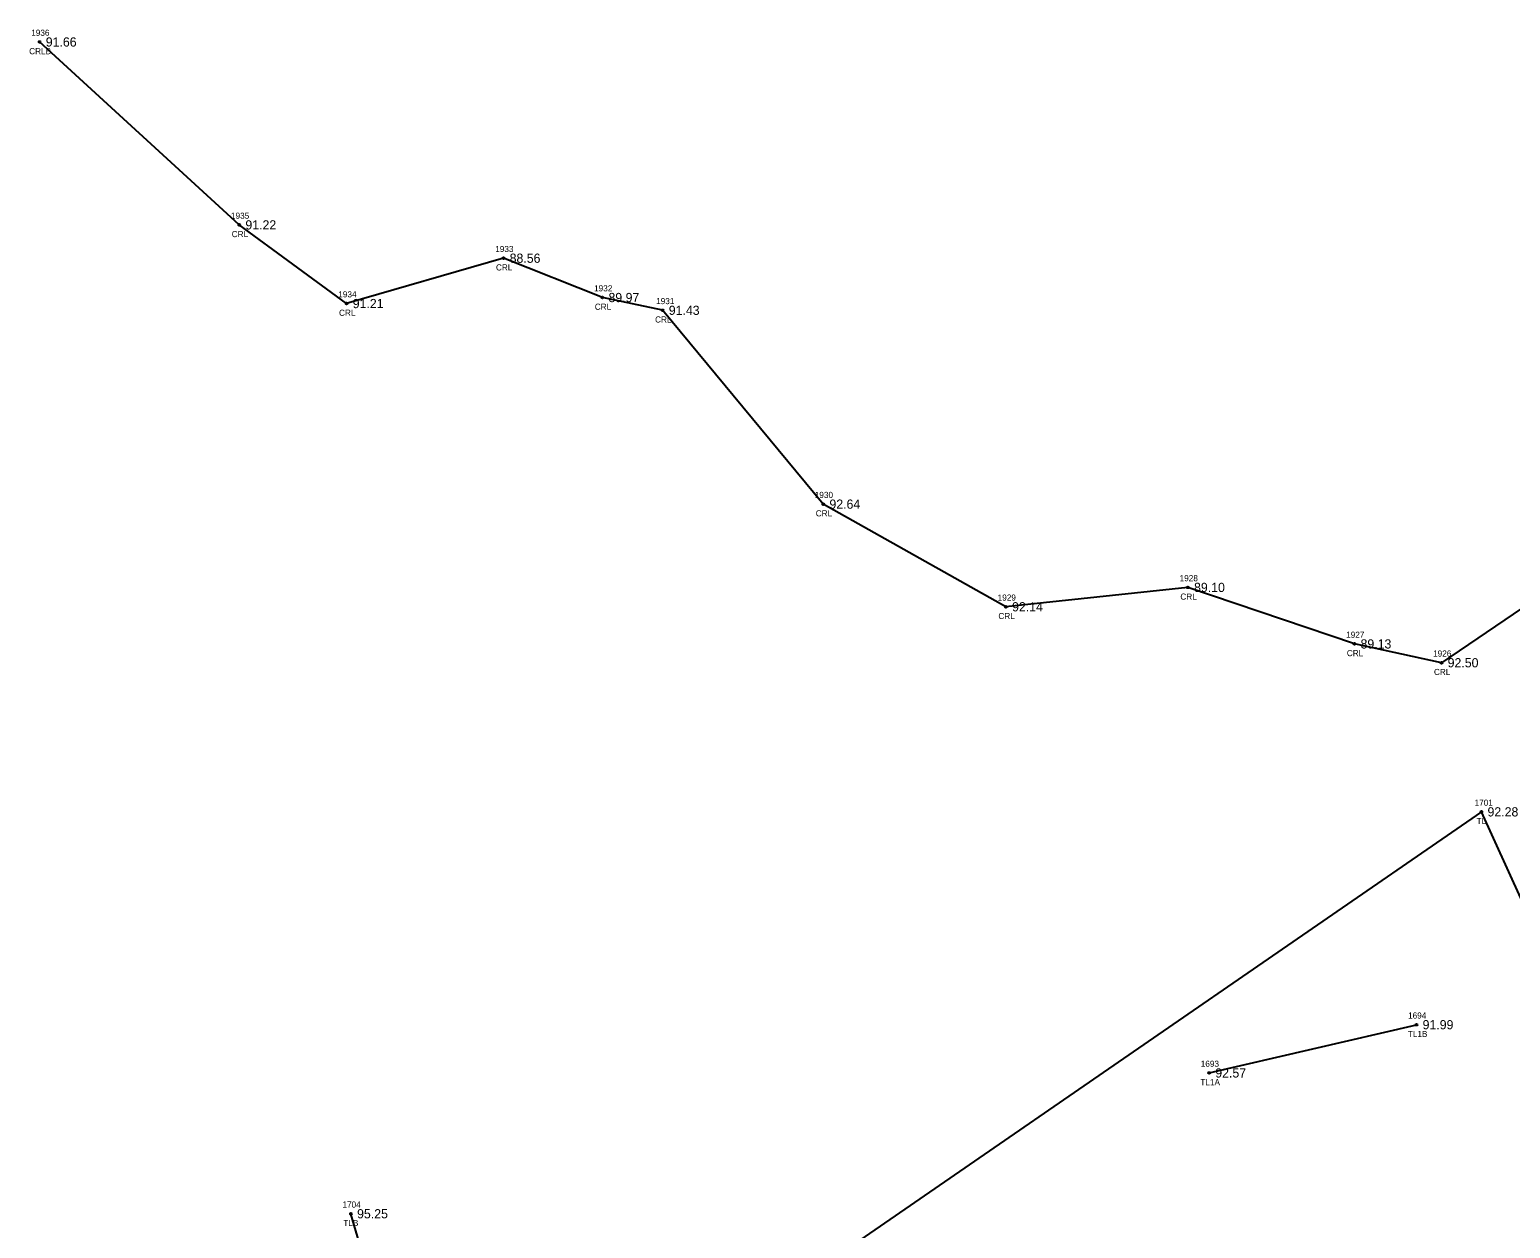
# Model space of a CAD drawing. Extents: x 2529517 to 2532038, y 935000 to 936944.
# Drawn here: x 2530793.2 to 2531034.4, y 935968.4 to 936163.8 of the extents above; entities that cross this region are included whole.
import ezdxf

# ---------------------------------------------------------------- set-up
doc = ezdxf.new("R2010")
doc.units = 0
for name, color, linetype in [('RD_EX_H2O', 7, 'Continuous'), ('RD_EX_H2O_txCode', 7, 'Continuous'), ('RD_EX_TX_H2O_ELEV', 7, 'Continuous'), ('RD_EX_TX_VEG_ELEV', 7, 'Continuous'), ('RD_EX_VEG', 7, 'Continuous'), ('RD_EX_VEG_txCode', 7, 'Continuous'), ('RD_SMD_Locator', 7, 'Continuous')]:
    doc.layers.add(name, color=color, linetype=linetype)

msp = doc.modelspace()

# ---------------------------------------------------------------- linework, layer by layer
at = {"layer": 'RD_EX_H2O'}
msp.add_lwpolyline([(2531078.88, 935952.28), (2531078.88, 935952.28), (2531082.9, 935955.37), (2531071.89, 935962.43), (2531052.52, 935981.82), (2531042.66, 936018.54), (2531050.4, 936038.59), (2531079.35, 936050.48), (2531076.46, 936052.29), (2531062.77, 936059.41), (2531060.27, 936060.12), (2531061.98, 936077.76), (2531053.99, 936081.48), (2531023.23, 936060.57), (2531009.04, 936063.64), (2530981.92, 936072.85), (2530952.28, 936069.69), (2530922.53, 936086.42), (2530896.36, 936118.01), (2530886.54, 936120.09), (2530870.44, 936126.5), (2530844.88, 936119.11), (2530827.4, 936131.93), (2530794.88, 936161.74)], dxfattribs=at)
at = {"layer": 'RD_EX_VEG'}
msp.add_line((2530985.38, 935993.72), (2531019.15, 936001.58), dxfattribs=at)
msp.add_lwpolyline([(2531065.97, 935956.74), (2531029.72, 936036.27), (2530913.11, 935955.89), (2530857.85, 935929), (2530845.59, 935970.77)], dxfattribs=at)
at = {"layer": 'RD_SMD_Locator'}
for centre in [(2530794.88, 936161.74), (2530827.4, 936131.93), (2530870.44, 936126.5), (2530844.88, 936119.11), (2530886.54, 936120.09), (2530896.36, 936118.01), (2530922.53, 936086.42), (2530981.92, 936072.85), (2530952.28, 936069.69), (2531009.04, 936063.64), (2531023.23, 936060.57), (2531029.72, 936036.27), (2531019.15, 936001.58), (2530985.38, 935993.72), (2530845.59, 935970.77)]:
    msp.add_circle(centre, 0.15, dxfattribs=at)

# ---------------------------------------------------------------- texts
at = {"layer": 'RD_EX_H2O_txCode'}
for s, p in [('1936', (2530793.51, 936162.74)), ('CRLB', (2530793.18, 936159.74)), ('1935', (2530826.05, 936132.93)), ('CRL', (2530826.17, 936129.93)), ('1933', (2530869.09, 936127.5)), ('CRL', (2530869.21, 936124.5)), ('1934', (2530843.53, 936120.11)), ('1932', (2530885.19, 936121.09)), ('CRL', (2530885.31, 936118.09)), ('1931', (2530895.3, 936119.01)), ('CRL', (2530843.65, 936117.11)), ('CRL', (2530895.13, 936116.01)), ('1930', (2530921.14, 936087.42)), ('CRL', (2530921.3, 936084.42)), ('1928', (2530980.57, 936073.85)), ('1929', (2530950.93, 936070.69)), ('CRL', (2530980.69, 936070.85)), ('CRL', (2530951.05, 936067.69)), ('1927', (2531007.69, 936064.64)), ('CRL', (2531007.81, 936061.64)), ('1926', (2531021.86, 936061.57)), ('CRL', (2531022, 936058.57))]:
    msp.add_text(s, height=1, dxfattribs=at).set_placement(p)
at = {"layer": 'RD_EX_TX_H2O_ELEV'}
for s, p in [('91.66', (2530795.88, 936160.99)), ('91.22', (2530828.4, 936131.18)), ('88.56', (2530871.44, 936125.75)), ('89.97', (2530887.54, 936119.34)), ('91.21', (2530845.88, 936118.36)), ('91.43', (2530897.36, 936117.26)), ('92.64', (2530923.53, 936085.67)), ('89.10', (2530982.92, 936072.1)), ('92.14', (2530953.28, 936068.94)), ('89.13', (2531010.04, 936062.89)), ('92.50', (2531024.23, 936059.82))]:
    msp.add_text(s, height=1.5, dxfattribs=at).set_placement(p)
at = {"layer": 'RD_EX_TX_VEG_ELEV'}
for s, p in [('92.28', (2531030.72, 936035.52)), ('91.99', (2531020.15, 936000.83)), ('92.57', (2530986.38, 935992.97)), ('95.25', (2530846.59, 935970.02))]:
    msp.add_text(s, height=1.5, dxfattribs=at).set_placement(p)
at = {"layer": 'RD_EX_VEG_txCode'}
for s, p in [('1701', (2531028.62, 936037.27)), ('TL', (2531028.95, 936034.27)), ('1694', (2531017.78, 936002.58)), ('TL1B', (2531017.74, 935999.58)), ('1693', (2530984.01, 935994.72)), ('TL1A', (2530983.95, 935991.72)), ('1704', (2530844.21, 935971.77)), ('TLB', (2530844.35, 935968.77))]:
    msp.add_text(s, height=1, dxfattribs=at).set_placement(p)

doc.saveas('drawing.dxf')
